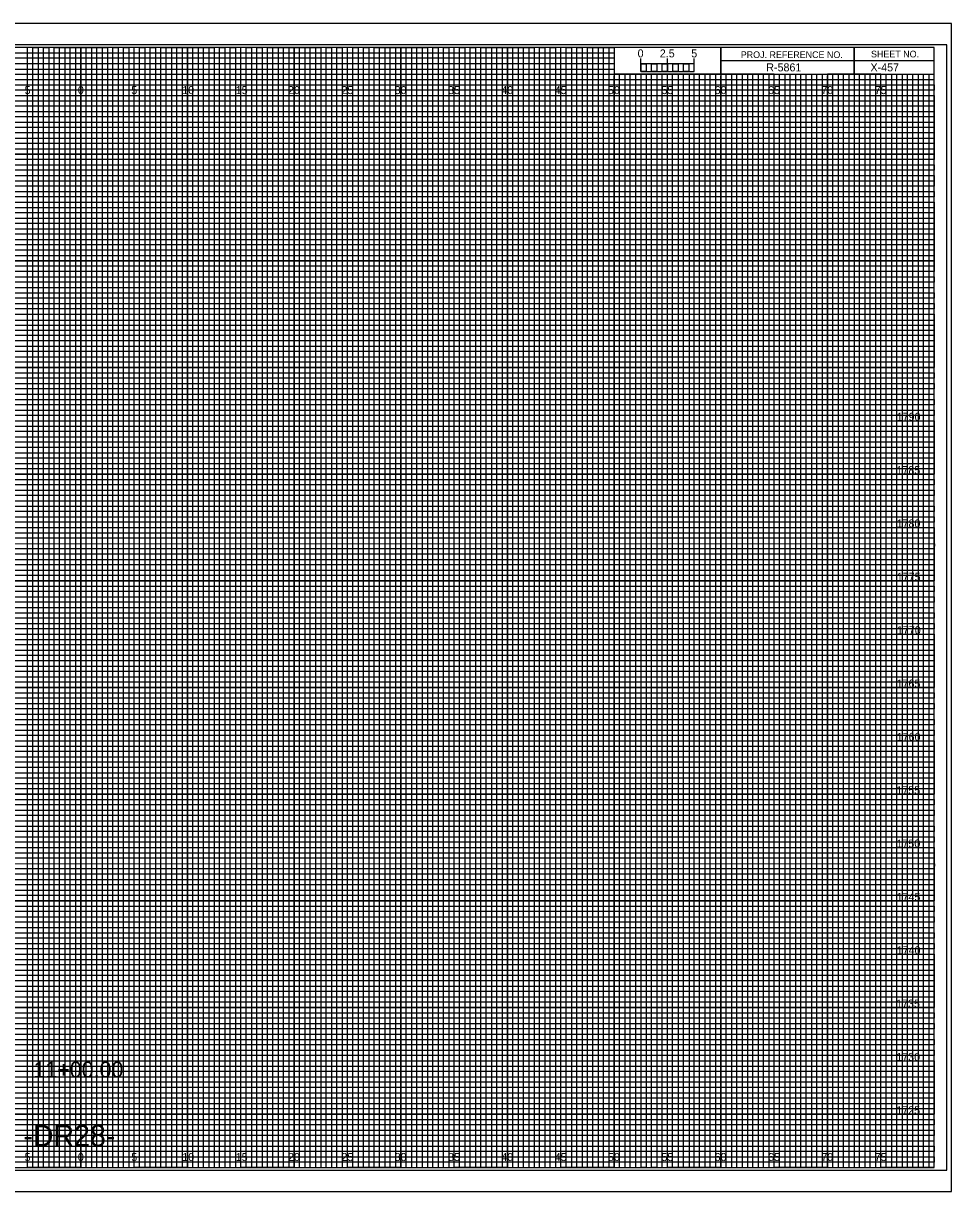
# Model space of a CAD drawing. Extents: x -7 to 162, y -2 to 547.
# Drawn here: x 74.6 to 161.7, y 107.7 to 217.2 of the extents above; entities that cross this region are included whole.
import ezdxf

# ---------------------------------------------------------------- set-up
doc = ezdxf.new("R2010")
doc.units = 0
for name, color, linetype in [('Prop Horizontal Alignment', 7, 'Continuous'), ('Prop XS Alignment Label', 7, 'Continuous'), ('Prop XS Bar Scale Labels', 7, 'Continuous'), ('Prop XS Gore Control Minimum', 7, 'Continuous'), ('Prop XS Project Number', 7, 'Continuous'), ('Prop XS Sheet Number', 7, 'Continuous'), ('Prop XS Shoulder Borrow Shape', 7, 'Continuous'), ('Raster_Level_0', 7, 'Continuous'), ('Scratch_Level_3', 7, 'Continuous'), ('Sheet Cross Section CELL', 7, 'Continuous'), ('Sheet Cross Section Grid Minor 1 CELL', 7, 'Continuous'), ('Sheet Cross Section Grid Minor 2 CELL', 7, 'Continuous'), ('Sheet Cross Section Scale CELL', 7, 'Continuous'), ('Sheet Cutting Line CELL', 7, 'Continuous'), ('Sheet DOT Grid CELL', 7, 'Continuous'), ('Sheet Plot Border Inside CELL', 7, 'Continuous'), ('Sheet Plot Border Outside CELL', 7, 'Continuous')]:
    doc.layers.add(name, color=color, linetype=linetype)

msp = doc.modelspace()

# ---------------------------------------------------------------- linework, layer by layer
at = {"layer": 'Prop XS Gore Control Minimum'}
for p, q in [((75, 215), (70, 215)), ((75, 110), (75, 215)), ((85, 215), (80, 215)), ((80, 215), (80, 110)), ((85, 110), (85, 215)), ((95, 215), (90, 215)), ((90, 215), (90, 110)), ((95, 110), (95, 215)), ((105, 215), (100, 215)), ((100, 215), (100, 110)), ((105, 110), (105, 215)), ((115, 215), (110, 215)), ((110, 215), (110, 110)), ((115, 110), (115, 215)), ((125, 215), (120, 215)), ((120, 215), (120, 110)), ((125, 110), (125, 215)), ((130, 215), (130, 110)), ((135, 110), (135, 212.5)), ((145, 212.5), (140, 212.5)), ((140, 212.5), (140, 110)), ((145, 110), (145, 212.5)), ((155, 212.5), (150, 212.5)), ((150, 212.5), (150, 110)), ((155, 110), (155, 212.5)), ((80, 110), (75, 110)), ((90, 110), (85, 110)), ((100, 110), (95, 110)), ((110, 110), (105, 110)), ((120, 110), (115, 110)), ((130, 110), (125, 110)), ((140, 110), (135, 110)), ((150, 110), (145, 110)), ((160, 110), (155, 110)), ((160, 110), (160, 110))]:
    msp.add_line(p, q, dxfattribs=at)
for points in [[(0, 210), (160, 210), (160, 205), (0, 205)], [(0, 200), (160, 200), (160, 195), (0, 195)], [(0, 190), (160, 190), (160, 185), (0, 185)], [(0, 180), (160, 180), (160, 175), (0, 175)], [(0, 170), (160, 170), (160, 165), (0, 165)], [(0, 160), (160, 160), (160, 155), (0, 155)], [(0, 150), (160, 150), (160, 145), (0, 145)], [(0, 140), (160, 140), (160, 135), (0, 135)], [(0, 130), (160, 130), (160, 125), (0, 125)], [(0, 120), (160, 120), (160, 115), (0, 115)]]:
    msp.add_lwpolyline(points, dxfattribs=at)
at = {"layer": 'Prop XS Shoulder Borrow Shape'}
for points in [[(72.5, 110), (77.5, 110), (77.5, 215), (82.5, 215), (82.5, 110), (87.5, 110), (87.5, 215), (92.5, 215), (92.5, 110), (97.5, 110), (97.5, 215), (102.5, 215), (102.5, 110), (107.5, 110), (107.5, 215), (112.5, 215), (112.5, 110), (117.5, 110), (117.5, 215), (122.5, 215), (122.5, 110), (127.5, 110), (127.5, 215), (129.97, 215), (130, 215), (130, 212.5), (132.5, 212.5), (132.5, 110), (137.5, 110), (137.5, 212.5), (142.5, 212.5), (142.5, 110), (147.5, 110), (147.5, 212.5), (152.5, 212.5), (152.5, 110), (157.5, 110), (157.5, 212.5)], [(0, 212.5), (137.5, 212.5)], [(0, 202.5), (160, 202.5), (160, 207.5), (0, 207.5)], [(0, 192.5), (160, 192.5), (160, 197.5), (0, 197.5)], [(0, 182.5), (160, 182.5), (160, 187.5), (0, 187.5)], [(0, 172.5), (160, 172.5), (160, 177.5), (0, 177.5)], [(0, 162.5), (160, 162.5), (160, 167.5), (0, 167.5)], [(0, 152.5), (160, 152.5), (160, 157.5), (0, 157.5)], [(0, 142.5), (160, 142.5), (160, 147.5), (0, 147.5)], [(0, 132.5), (160, 132.5), (160, 137.5), (0, 137.5)], [(0, 122.5), (160, 122.5), (160, 127.5), (0, 127.5)], [(0, 112.5), (160, 112.5), (160, 117.5), (0, 117.5)]]:
    msp.add_lwpolyline(points, dxfattribs=at)
at = {"layer": 'Sheet Cross Section CELL'}
for p, q in [((152.5, 215), (152.5, 212.5)), ((152.5, 212.5), (152.5, 215)), ((160, 213.75), (140, 213.75)), ((140, 213.75), (140, 212.5)), ((140, 212.5), (160, 212.5))]:
    msp.add_line(p, q, dxfattribs=at)
for points in [[(160, 215), (0, 215), (0, 110), (160, 110)], [(140, 215), (130, 215), (130, 212.52), (140, 212.52)], [(160, 215), (140, 215), (140, 212.5), (160, 212.5)]]:
    msp.add_lwpolyline(points, close=True, dxfattribs=at)
at = {"layer": 'Sheet Cross Section Grid Minor 1 CELL'}
for p, q in [((0, 214.5), (130, 214.5)), ((130, 213.99), (0, 213.99)), ((130, 214.5), (130, 213.99)), ((0, 213.5), (130, 213.5)), ((130, 212.94), (0, 212.94)), ((130, 213.5), (130, 212.94)), ((0, 212), (160, 212))]:
    msp.add_line(p, q, dxfattribs=at)
for points in [[(0, 211.5), (135, 211.5), (160, 211.5), (160, 211), (0, 211)], [(0, 210.5), (160, 210.5), (160, 209.5), (0, 209.5)], [(0, 209), (160, 209), (160, 208.5), (0, 208.49)], [(0, 208), (160, 208), (160, 207), (0, 207)], [(0, 206.5), (160, 206.5), (160, 206), (0, 206)], [(0, 205.5), (160, 205.5), (160, 204.5), (0, 204.5)], [(0, 204), (160, 204), (160, 203.5), (0, 203.5)], [(0, 203), (160, 203), (160, 202), (0, 202)], [(0, 201.5), (160, 201.5), (160, 201), (0, 201)], [(0, 200.5), (160, 200.5), (160, 199.5), (0, 199.5)], [(0, 199), (160, 199), (160, 198.5), (0, 198.5)], [(0, 198), (160, 198), (160, 196.97), (160, 196.5), (160, 196), (0, 196)], [(0, 197), (160, 197), (160, 196.5), (0, 196.5)], [(0, 195.5), (160, 195.5), (160, 194.5), (0, 194.52)], [(0, 194.52), (160, 194.5), (160, 194), (0, 194)], [(0, 193.5), (160, 193.5), (160, 193), (0, 193)], [(0, 192), (160, 192), (160, 191.5), (0, 191.5)], [(0, 191), (160, 191), (160, 190.5), (0, 190.5)], [(-0.04, 189.44), (160, 189.44), (160, 188.94), (-0.04, 188.94)], [(0, 188.5), (160, 188.5), (160, 188), (0, 188)], [(0, 187), (160, 187), (160, 186.5), (0, 186.5)], [(0, 186), (160, 186), (160, 185.5), (0, 185.5)], [(0, 184.5), (160, 184.5), (160, 184), (0, 184)], [(0, 183.5), (160, 183.5), (160, 183), (0, 183)], [(0, 182), (160, 182), (160, 181.5), (0, 181.5)], [(0, 181), (160, 181), (160, 180.5), (0, 180.5)], [(0, 179.5), (160, 179.5), (160, 178.99), (0, 179)], [(0, 178.5), (160, 178.5), (160, 178), (0, 178)], [(0, 177), (160, 177), (160, 176.5), (0, 176.5)], [(0, 176), (160, 176), (160, 175.5), (0, 175.5)], [(0, 174.5), (160, 174.5), (160, 174), (0, 174)], [(0, 173.5), (160, 173.5), (160, 173), (0, 173)], [(0, 172), (160, 172), (160, 171.5), (0, 171.5)], [(0, 171), (160, 171), (160, 170.5), (0, 170.5)], [(0, 169.5), (160, 169.5), (160, 169), (0, 169)], [(0, 168.5), (160.03, 168.46), (160, 168), (0, 168)], [(0, 167), (160, 167), (160, 166.5), (0, 166.5)], [(0, 166), (160, 166), (160, 165.5), (0, 165.5)], [(0, 164.5), (160, 164.5), (160, 164), (0, 164)], [(0, 163.5), (160, 163.5), (160, 163), (0, 163)], [(0, 162), (160, 162), (160, 161.5), (0, 161.5)], [(0, 161), (160, 161), (160, 160.5), (0, 160.5)], [(0, 159.5), (160, 159.5), (160, 159), (0, 159)], [(0, 158.5), (160, 158.5), (160, 158), (0, 158)], [(0, 157), (160, 157), (160, 156.5), (0, 156.5)], [(0, 156), (160, 156), (160, 155.5), (0, 155.5)], [(0, 154.5), (160, 154.5), (160, 154), (0, 154)], [(0, 153.5), (160, 153.5), (160, 153), (0, 153)], [(0, 152), (160, 152), (160, 151.5), (0, 151.5)], [(0, 151), (160, 151), (160, 150.5), (0, 150.5)], [(0, 149.5), (160, 149.5), (160, 148.99), (0, 149)], [(0, 148.5), (160, 148.5), (160, 148), (0, 148)], [(0, 147), (160, 147), (160, 146.5), (0, 146.5)], [(0, 146), (160, 146), (160, 145.5), (0, 145.5)], [(0, 144.5), (160, 144.5), (160, 144), (0, 144)], [(0, 143.5), (160, 143.5), (160, 143), (0, 143)], [(0, 142), (160, 142), (160, 141.5), (0, 141.5)], [(0, 141), (160, 141), (160, 140.5), (0, 140.5)], [(0, 139.5), (160, 139.5), (160, 139), (0, 139)], [(0, 138.5), (160.03, 138.46), (160, 138), (0, 138)], [(0, 137), (160, 137), (160, 136.5), (0, 136.5)], [(0, 136), (160, 136), (160, 135.5), (0, 135.5)], [(0, 134.5), (160, 134.5), (160, 134), (0, 134)], [(0, 133.5), (160, 133.5), (160, 133), (0, 133)], [(0, 132), (160, 132), (160, 131.5), (0, 131.5)], [(0, 131), (160, 131), (160, 130.5), (0, 130.5)], [(0, 129.5), (160, 129.5), (160, 129), (0, 129)], [(0, 128.5), (160, 128.5), (160, 128), (0, 128)], [(0, 127), (160, 127), (160, 126.5), (0, 126.5)], [(0, 126), (160, 126), (160, 125.5), (0, 125.5)], [(0, 124.5), (160, 124.5), (160, 124), (0, 124)], [(0, 123.5), (160, 123.5), (160, 123), (0, 123)], [(0, 122), (160, 122), (160, 121.5), (0, 121.5)], [(0, 121), (160, 121), (160, 120.5), (0, 120.5)], [(0, 119.5), (160, 119.5), (160, 119), (0, 119)], [(0, 118.5), (160, 118.5), (160, 118), (0, 118)], [(0, 117), (160, 117), (160, 116.5), (0, 116.5)], [(0, 116), (160, 116), (160, 115.5), (0, 115.5)], [(0, 114.5), (160, 114.5), (160, 114), (0, 114)], [(0, 113.5), (160, 113.5), (160, 113), (0, 113)], [(0, 112), (160, 112), (160, 111.5), (0, 111.5)], [(0, 111), (160, 111), (160, 110.5), (0, 110.5)]]:
    msp.add_lwpolyline(points, dxfattribs=at)
at = {"layer": 'Sheet Cross Section Grid Minor 2 CELL'}
for p, q in [((133.5, 212.5), (133, 212.5)), ((133, 212.5), (133, 110)), ((133.5, 110), (133.5, 212.5)), ((134.5, 212.5), (134, 212.5)), ((134, 212.5), (134, 110)), ((134.5, 110), (134.5, 212.5)), ((133, 110), (132.5, 110)), ((134, 110), (133.5, 110))]:
    msp.add_line(p, q, dxfattribs=at)
for points in [[(75, 110), (75.5, 110), (75.5, 215), (76, 215), (76, 110)], [(76, 110), (76.5, 110), (76.5, 215), (77, 215), (77, 110)], [(77.5, 110), (78, 110), (78, 215), (78.5, 215), (78.5, 110)], [(78.5, 110), (79, 110), (79, 215), (79.5, 215), (79.5, 110)], [(80, 110), (80.5, 110), (80.5, 215), (81, 215), (81, 110)], [(81, 110), (81.5, 110), (81.5, 215), (82, 215), (82, 110)], [(82.5, 110), (83, 110), (83, 215), (83.5, 215), (83.5, 110)], [(83.5, 110), (84, 110), (84, 215), (84.5, 215), (84.5, 110)], [(85, 110), (85.5, 110), (85.5, 215), (86, 215), (86, 110)], [(86, 110), (86.5, 110), (86.5, 215), (87, 215), (87, 110)], [(87.5, 110), (88, 110), (88, 215), (88.5, 215), (88.5, 110)], [(88.5, 110), (89, 110), (89, 215), (89.5, 215), (89.5, 110)], [(90, 110), (90.5, 110), (90.5, 215), (91, 215), (91, 110)], [(91, 110), (91.5, 110), (91.5, 215), (92, 215), (92, 110)], [(92.5, 110), (93, 110), (93, 215), (93.5, 215), (93.5, 110)], [(93.5, 110), (94, 110), (94, 215), (94.5, 215), (94.5, 110)], [(95, 110), (95.5, 110), (95.5, 215), (96, 215), (96, 110)], [(96, 110), (96.5, 110), (96.5, 215), (97, 215), (97, 110)], [(97.5, 110), (98, 110), (98, 215), (98.5, 215), (98.5, 110)], [(98.5, 110), (99, 110), (99, 215), (99.5, 215), (99.5, 110)], [(100, 110), (100.5, 110), (100.5, 215), (101, 215), (101, 110)], [(101, 110), (101.5, 110), (101.5, 215), (102, 215), (102, 110)], [(102.5, 110), (103, 110), (103, 215), (103.5, 215), (103.5, 110)], [(103.5, 110), (104, 110), (104, 215), (104.5, 215), (104.5, 110)], [(105, 110), (105.5, 110), (105.5, 215), (106, 215), (106, 110)], [(106, 110), (106.5, 110), (106.5, 215), (107, 215), (107, 110)], [(107.5, 110), (108, 110), (108, 215), (108.5, 215), (108.5, 110)], [(108.5, 110), (109, 110), (109, 215), (109.5, 215), (109.5, 110)], [(110, 110), (110.5, 110), (110.5, 215), (111, 215), (111, 110)], [(111, 110), (111.5, 110), (111.5, 215), (112, 215), (112, 110)], [(112.5, 110), (113, 110), (113, 215), (113.5, 215), (113.5, 110)], [(113.5, 110), (114, 110), (114, 215), (114.5, 215), (114.5, 110)], [(115, 110), (115.5, 110), (115.5, 215), (116, 215), (116, 110)], [(116, 110), (116.5, 110), (116.5, 215), (117, 215), (117, 110)], [(117.5, 110), (118, 110), (118, 215), (118.5, 215), (118.5, 110)], [(118.5, 110), (119, 110), (119, 215), (119.5, 215), (119.5, 110)], [(120, 110), (120.5, 110), (120.5, 215), (121, 215), (121, 110)], [(121, 110), (121.5, 110), (121.5, 215), (122, 215), (122, 110)], [(122.5, 110), (123, 110), (123, 215), (123.5, 215), (123.5, 110)], [(123.5, 110), (124, 110), (124, 215), (124.5, 215), (124.5, 110)], [(125, 110), (125.5, 110), (125.5, 215), (126, 215), (126, 110)], [(126, 110), (126.5, 110), (126.5, 215), (127, 215), (127, 110)], [(127.5, 110), (128, 110), (128, 215), (128.5, 215), (128.5, 110)], [(128.5, 110), (129, 110), (129, 215), (129.5, 215), (129.5, 110)], [(130, 110), (130.5, 110), (130.5, 212.5), (131.01, 212.5), (131.01, 110)], [(131, 110), (131.5, 110), (131.5, 212.5), (132, 212.5), (132, 110)], [(135, 110), (135.49, 110), (135.49, 212.5), (136, 212.5), (136, 110)], [(136, 110), (136.5, 110), (136.5, 212.5), (137.03, 212.5), (137.03, 110)], [(137.5, 110), (138, 110), (138, 212.5), (138.5, 212.5), (138.5, 110)], [(138.5, 110), (139, 110), (139, 212.5), (139.5, 212.5), (139.5, 110)], [(140, 110), (140.5, 110), (140.5, 212.5), (141, 212.5), (141, 110)], [(141, 110), (141.5, 110), (141.5, 212.5), (142, 212.5), (142, 110)], [(142.5, 110), (143, 110), (143, 212.5), (143.5, 212.5), (143.5, 110)], [(143.5, 110), (144, 110), (144, 212.5), (144.5, 212.5), (144.5, 110)], [(145, 110), (145.5, 110), (145.5, 212.5), (146, 212.5), (146, 110)], [(146, 110), (146.5, 110), (146.5, 212.5), (147, 212.5), (147, 110)], [(147.5, 110), (148, 110), (148, 212.5), (148.5, 212.5), (148.5, 110)], [(148.5, 110), (149, 110), (149, 212.5), (149.5, 212.5), (149.5, 110)], [(150, 110), (150.5, 110), (150.5, 212.5), (151, 212.5), (151, 110)], [(151, 110), (151.5, 110), (151.5, 212.5), (152, 212.5), (152, 110)], [(152.5, 110), (153, 110), (153, 212.5), (153.5, 212.5), (153.5, 110)], [(153.5, 110), (154, 110), (154, 212.5), (154.5, 212.5), (154.5, 110)], [(155, 110), (155.5, 110), (155.5, 212.5), (156, 212.5), (156, 110)], [(156, 110), (156.5, 110), (156.5, 212.5), (157, 212.5), (157, 110)], [(157.5, 110), (158, 110), (158, 212.5), (158.5, 212.5), (158.5, 110)], [(158.5, 110), (159, 110), (159, 212.5), (159.5, 212.5), (159.5, 110)]]:
    msp.add_lwpolyline(points, dxfattribs=at)
at = {"layer": 'Sheet Cross Section Scale CELL'}
for p, q in [((132.5, 212.75), (132.5, 213.95)), ((132.5, 213.45), (132.5, 213.95)), ((135, 212.75), (135, 213.95)), ((137.5, 212.75), (137.5, 213.95)), ((137.5, 213.45), (137.5, 213.95))]:
    msp.add_line(p, q, dxfattribs=at)
for points in [[(137.5, 213.45), (132.5, 213.45), (132.5, 212.75), (137.5, 212.75)], [(132.5, 213.45), (133, 213.45), (133, 212.75), (132.5, 212.75)], [(133.5, 213.45), (134, 213.45), (134, 212.75), (133.5, 212.75)], [(134.5, 213.45), (135, 213.45), (135, 212.75), (134.5, 212.75)], [(135.5, 213.45), (136, 213.45), (136, 212.75), (135.5, 212.75)], [(136.5, 213.45), (137, 213.45), (137, 212.75), (136.5, 212.75)]]:
    msp.add_lwpolyline(points, close=True, dxfattribs=at)
at = {"layer": 'Sheet Cutting Line CELL'}
for p, q in [((161.65, 217.25), (-6.7, 217.25)), ((-6.7, 107.75), (161.65, 107.75))]:
    msp.add_line(p, q, dxfattribs=at)
at = {"layer": 'Sheet DOT Grid CELL'}
for p, q in [((75, 110), (75, 215)), ((80, 110), (80, 215)), ((85, 110), (85, 215)), ((90, 110), (90, 215)), ((95, 110), (95, 215)), ((100, 110), (100, 215)), ((105, 110), (105, 215)), ((110, 110), (110, 215)), ((115, 110), (115, 215)), ((120, 110), (120, 215)), ((125, 110), (125, 215)), ((130, 110), (130, 212.34)), ((135, 110), (135, 212.34)), ((140, 110), (140, 212.34)), ((145, 110), (145, 212.34)), ((150, 110), (150, 212.34)), ((155, 110), (155, 212.34)), ((0, 210), (160, 210)), ((0, 205), (160, 205)), ((0, 200), (160, 200)), ((0, 195), (160, 195)), ((0, 190), (160, 190)), ((0, 185), (160, 185)), ((0, 180), (160, 180)), ((0, 175), (160, 175)), ((0, 170), (160, 170)), ((0, 165), (160, 165)), ((0, 160), (160, 160)), ((0, 155), (160, 155)), ((0, 150), (160, 150)), ((0, 145), (160, 145)), ((0, 140), (160, 140)), ((0, 135), (160, 135)), ((0, 130), (160, 130)), ((0, 125), (160, 125)), ((0, 120), (160, 120)), ((0, 115), (160, 115))]:
    msp.add_line(p, q, dxfattribs=at)
at = {"layer": 'Sheet Plot Border Inside CELL'}
msp.add_lwpolyline([(-5.4, 109.75), (161.2, 109.75), (161.2, 215.25), (-5.4, 215.25)], close=True, dxfattribs=at)
at = {"layer": 'Sheet Plot Border Outside CELL'}
msp.add_lwpolyline([(-6.7, 107.75), (161.65, 107.75), (161.65, 217.25), (-6.7, 217.25)], close=True, dxfattribs=at)

# ---------------------------------------------------------------- texts
at = {"layer": 'Prop Horizontal Alignment'}
msp.add_text('11+00.00', height=1.5, dxfattribs=at).set_placement((75.57, 118.44))
at = {"layer": 'Prop XS Alignment Label'}
msp.add_text('-DR28-', height=2, dxfattribs=at).set_placement((74.62, 112))
at = {"layer": 'Prop XS Bar Scale Labels'}
for s, p in [('2.5', (134.29, 214.06)), ('5', (137.24, 214.06))]:
    msp.add_text(s, height=0.75, dxfattribs=at).set_placement(p)
at = {"layer": 'Prop XS Project Number'}
msp.add_text('R-5861', height=0.75, dxfattribs=at).set_placement((144.27, 212.75))
at = {"layer": 'Prop XS Sheet Number'}
msp.add_text('X-457', height=0.75, dxfattribs=at).set_placement((154.04, 212.75))
at = {"layer": 'Raster_Level_0'}
for s, p in [('5', (74.74, 210.62)), ('0', (79.73, 210.62)), ('0', (79.73, 210.62)), ('5', (84.74, 210.62)), ('10', (89.52, 210.62)), ('15', (94.53, 210.62)), ('20', (99.43, 210.62)), ('25', (104.44, 210.62)), ('30', (109.43, 210.62)), ('35', (114.44, 210.62)), ('40', (119.43, 210.62)), ('45', (124.44, 210.62)), ('50', (129.43, 210.62)), ('55', (134.44, 210.62)), ('60', (139.43, 210.62)), ('65', (144.44, 210.62)), ('70', (149.43, 210.62)), ('75', (154.44, 210.62)), ('5', (74.74, 110.62)), ('0', (79.73, 110.62)), ('0', (79.73, 110.62)), ('5', (84.74, 110.62)), ('10', (89.52, 110.62)), ('15', (94.53, 110.62)), ('20', (99.43, 110.62)), ('25', (104.44, 110.62)), ('30', (109.43, 110.62)), ('35', (114.44, 110.62)), ('40', (119.43, 110.62)), ('45', (124.44, 110.62)), ('50', (129.43, 110.62)), ('55', (134.44, 110.62)), ('60', (139.43, 110.62)), ('65', (144.44, 110.62)), ('70', (149.43, 110.62)), ('75', (154.44, 110.62))]:
    msp.add_text(s, height=0.75, dxfattribs=at).set_placement(p)
at = {"layer": 'Scratch_Level_3'}
for s, p in [('1790', (156.5, 180)), ('1785', (156.48, 175)), ('1780', (156.49, 170)), ('1775', (156.51, 165)), ('1770', (156.52, 160)), ('1765', (156.49, 155)), ('1760', (156.5, 150)), ('1755', (156.47, 145)), ('1750', (156.48, 140)), ('1745', (156.49, 135)), ('1740', (156.5, 130)), ('1735', (156.45, 125)), ('1730', (156.46, 120)), ('1725', (156.46, 115))]:
    msp.add_text(s, height=0.75, dxfattribs=at).set_placement(p)
at = {"layer": 'Sheet Cross Section CELL'}
for s, p in [('PROJ. REFERENCE NO.', (141.88, 214)), ('SHEET NO.', (154.09, 214.06))]:
    msp.add_text(s, height=0.625, dxfattribs=at).set_placement(p)
at = {"layer": 'Sheet Cross Section Scale CELL'}
msp.add_text('0', height=0.75, dxfattribs=at).set_placement((132.21, 214.06))

doc.saveas('drawing.dxf')
